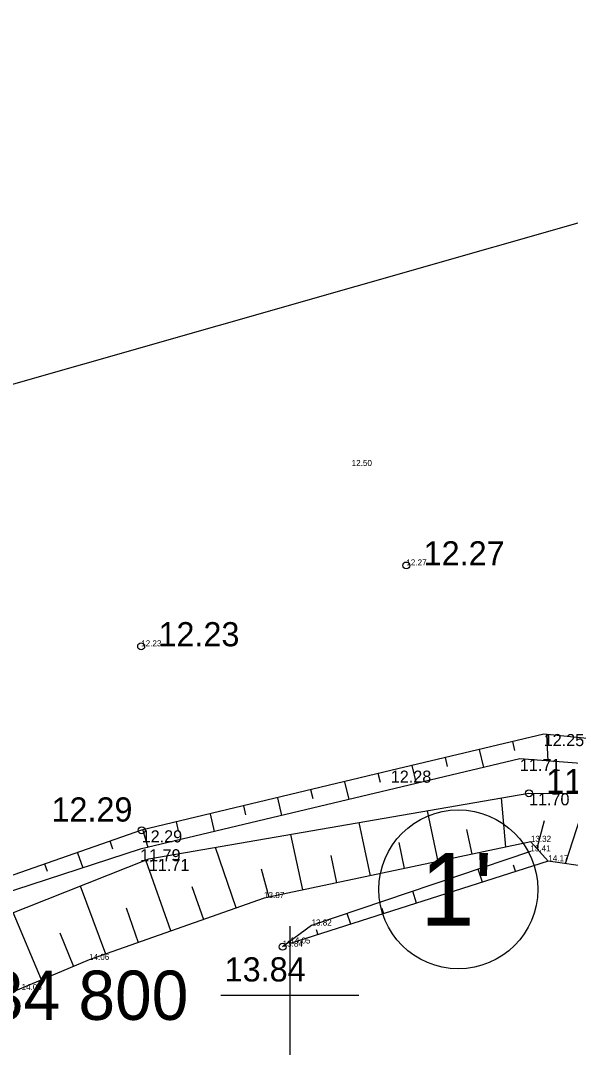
# Model space of a CAD drawing. Extents: x 433497 to 434382, y 6534486 to 6534993.
# Drawn here: x 433584.4 to 433616.2, y 6534797 to 6534856.4 of the extents above; entities that cross this region are included whole.
import ezdxf

# ---------------------------------------------------------------- set-up
doc = ezdxf.new("R2010")
doc.units = 0
for name, color, linetype in [('KORGUS-EH2000', 7, 'Continuous'), ('MOOTKORG-EH2000', 7, 'Continuous'), ('PIIR', 7, 'Continuous'), ('RELJEEF', 7, 'Continuous'), ('VEEKOGU', 7, 'Continuous'), ('VORK', 7, 'Continuous'), ('VORMISTUS', 7, 'Continuous')]:
    doc.layers.add(name, color=color, linetype=linetype)

msp = doc.modelspace()

# ---------------------------------------------------------------- linework, layer by layer
at = {"layer": 'KORGUS-EH2000'}
for centre in [(433606.74, 6534824.87), (433591.4, 6534820.19), (433613.835, 6534811.689), (433591.428, 6534809.544), (433599.582, 6534802.808)]:
    msp.add_circle(centre, 0.2, dxfattribs=at)
at = {"layer": 'PIIR'}
msp.add_circle((433609.747, 6534806.124), 4.6, dxfattribs=at)
at = {"layer": 'RELJEEF'}
for p, q in [((433613.011, 6534814.159), (433612.892, 6534814.688)), ((433614.84, 6534815.101), (433614.925, 6534813.55)), ((433610.947, 6534814.222), (433611.198, 6534813.172)), ((433609.127, 6534813.232), (433609.002, 6534813.756)), ((433607.057, 6534813.29), (433607.307, 6534812.246)), ((433603.167, 6534812.358), (433603.415, 6534811.321)), ((433605.236, 6534812.304), (433605.112, 6534812.824)), ((433601.346, 6534811.375), (433601.222, 6534811.892)), ((433615.944, 6534807.614), (433617.266, 6534811.67)), ((433599.277, 6534811.426), (433599.524, 6534810.396)), ((433612.486, 6534808.569), (433612.248, 6534811.415)), ((433595.387, 6534810.493), (433595.632, 6534809.47)), ((433597.455, 6534810.446), (433597.332, 6534810.959)), ((433608.572, 6534807.744), (433607.955, 6534810.672)), ((433593.564, 6534809.517), (433593.442, 6534810.027)), ((433604.658, 6534806.919), (433604.011, 6534809.99)), ((433614.716, 6534810.089), (433614.285, 6534808.496)), ((433591.497, 6534809.561), (433591.79, 6534808.557)), ((433600.744, 6534806.094), (433600.067, 6534809.308)), ((433610.228, 6534809.585), (433610.529, 6534808.157)), ((433589.767, 6534808.448), (433589.607, 6534808.908)), ((433606.299, 6534808.831), (433606.615, 6534807.332)), ((433587.719, 6534808.249), (433588.026, 6534807.368)), ((433596.891, 6534805.052), (433595.691, 6534808.551)), ((433602.37, 6534808.078), (433602.701, 6534806.507)), ((433585.978, 6534807.169), (433585.831, 6534807.59)), ((433593.12, 6534803.719), (433591.672, 6534807.817)), ((433612.92, 6534807.547), (433613.048, 6534807.146)), ((433598.347, 6534807.308), (433598.787, 6534805.682)), ((433611.142, 6534806.539), (433610.898, 6534807.304)), ((433589.349, 6534802.386), (433587.894, 6534806.321)), ((433609.12, 6534806.297), (433609.237, 6534805.931)), ((433594.332, 6534806.292), (433595.006, 6534804.385)), ((433607.331, 6534805.324), (433607.109, 6534806.019)), ((433585.64, 6534800.89), (433584.003, 6534804.78)), ((433590.523, 6534805.066), (433591.234, 6534803.052)), ((433603.52, 6534804.109), (433603.321, 6534804.734)), ((433605.32, 6534805.047), (433605.426, 6534804.716)), ((433586.702, 6534803.603), (433587.484, 6534801.666)), ((433601.52, 6534803.796), (433601.615, 6534803.501)), ((433600.021, 6534802.993), (433599.986, 6534803.104))]:
    msp.add_line(p, q, dxfattribs=at)
for points in [[(433749.058, 6534856.332), (433741.841, 6534853.465), (433717.91, 6534845.411), (433702.328, 6534840.514), (433691.755, 6534835.121), (433679.525, 6534829.764), (433651.528, 6534818.64), (433637.327, 6534811.851), (433630.595, 6534812.126), (433622.045, 6534814.376), (433614.685, 6534815.117), (433605.841, 6534812.999), (433591.428, 6534809.544), (433575.413, 6534803.952), (433570.231, 6534802.507)], [(433641.312, 6534803.133), (433635.11, 6534803.273), (433622.185, 6534806.726), (433614.95, 6534807.755), (433613.943, 6534808.876), (433598.508, 6534805.623), (433588.385, 6534802.045), (433575.786, 6534796.741), (433561.572, 6534791.45), (433550.393, 6534787.427)], [(433613.913, 6534808.327), (433601.253, 6534804.033), (433599.582, 6534802.808)], [(433614.953, 6534807.754), (433600.021, 6534802.993)]]:
    msp.add_lwpolyline(points, dxfattribs=at)
at = {"layer": 'VEEKOGU'}
for points in [[(433749.058, 6534856.332), (433741.841, 6534853.465), (433722.771, 6534845.253), (433710.509, 6534841.204), (433704.412, 6534838.967), (433698.912, 6534836.045), (433689.963, 6534831.852), (433681.025, 6534828.643), (433674.289, 6534826.026), (433651.647, 6534816.525), (433637.528, 6534810.175), (433630.797, 6534811.068), (433623.412, 6534812.9), (433613.311, 6534813.674), (433591.338, 6534808.449), (433572.407, 6534802.271)], [(433572.968, 6534800.411), (433591.847, 6534807.886), (433613.835, 6534811.689), (433622.814, 6534811.64), (433631.731, 6534808.602), (433638.345, 6534808.16), (433643.538, 6534810.243), (433652.755, 6534814.828), (433676.018, 6534824.841), (433679.31, 6534824.215), (433682.459, 6534827.262), (433690.574, 6534830.588), (433710.129, 6534839.081), (433723.05, 6534843.918), (433736.064, 6534848.408), (433747.792, 6534853.33), (433748.765, 6534853.283)]]:
    msp.add_lwpolyline(points, dxfattribs=at)
at = {"layer": 'VORK'}
for p, q in [((433600, 6534804), (433600, 6534796)), ((433596, 6534800), (433604, 6534800))]:
    msp.add_line(p, q, dxfattribs=at)
at = {"layer": 'VORMISTUS'}
msp.add_lwpolyline([(433756.833, 6534894.348), (433691.203, 6534872.087), (433653.508, 6534864.187), (433636.546, 6534862.392), (433627.673, 6534847.824), (433564.128, 6534829.695), (433582.608, 6534768.478), (433587.883, 6534751.004), (433591.763, 6534747.472), (433594.096, 6534737.418), (433589.968, 6534732.121), (433592.57, 6534706.447), (433596.133, 6534671.303), (433599.93, 6534613.558), (433630.448, 6534534.937), (433664.149, 6534549.227), (433704.536, 6534572.568), (433752.081, 6534596.222), (433789.501, 6534614.839)], dxfattribs=at)
msp.add_lwpolyline([(433756.833, 6534894.348), (433691.203, 6534872.087), (433653.508, 6534864.187), (433636.546, 6534862.392), (433627.673, 6534847.824), (433564.128, 6534829.695), (433582.608, 6534768.478), (433587.883, 6534751.004), (433591.763, 6534747.472), (433594.096, 6534737.418), (433589.968, 6534732.121), (433592.57, 6534706.447), (433596.133, 6534671.303), (433599.93, 6534613.558), (433630.448, 6534534.937), (433664.149, 6534549.227), (433704.536, 6534572.568), (433752.081, 6534596.222), (433789.501, 6534614.839)], dxfattribs=at)

# ---------------------------------------------------------------- texts
at = {"layer": 'KORGUS-EH2000'}
for s, p in [('12.27', (433607.74, 6534824.87)), ('12.23', (433592.4, 6534820.19)), ('11.70', (433614.835, 6534811.689)), ('12.29', (433586.211, 6534810.05)), ('13.84', (433596.23, 6534800.796))]:
    msp.add_text(s, height=1.4, dxfattribs=at).set_placement(p)
at = {"layer": 'MOOTKORG-EH2000'}
for s, height, p in [('12.50', 0.35, (433603.578, 6534830.625)), ('12.27', 0.35, (433606.74, 6534824.87)), ('12.23', 0.35, (433591.4, 6534820.19)), ('12.25', 0.7, (433614.685, 6534814.417)), ('11.71', 0.7, (433613.311, 6534812.974)), ('12.28', 0.7, (433605.841, 6534812.299)), ('11.70', 0.7, (433613.835, 6534810.989)), ('12.29', 0.7, (433591.428, 6534808.844)), ('13.41', 0.35, (433613.913, 6534808.327)), ('13.32', 0.35, (433613.943, 6534808.876)), ('11.79', 0.7, (433591.338, 6534807.749)), ('14.17', 0.35, (433614.95, 6534807.755)), ('14.17', 0.35, (433614.953, 6534807.754)), ('11.71', 0.7, (433591.847, 6534807.186)), ('13.87', 0.35, (433598.508, 6534805.623)), ('13.82', 0.35, (433601.253, 6534804.033)), ('14.05', 0.35, (433600.021, 6534802.993)), ('13.84', 0.35, (433599.582, 6534802.808)), ('14.06', 0.35, (433588.385, 6534802.045)), ('14.05', 0.35, (433584.479, 6534800.306))]:
    msp.add_text(s, height=height, dxfattribs=at).set_placement(p)
at = {"layer": 'PIIR'}
msp.add_text("1'", height=4.2, dxfattribs=at).set_placement((433607.546, 6534804.024))
at = {"layer": 'VORK'}
msp.add_text('6 534 800 ', height=2.85, dxfattribs=at).set_placement((433577.174, 6534798.575))

doc.saveas('drawing.dxf')
